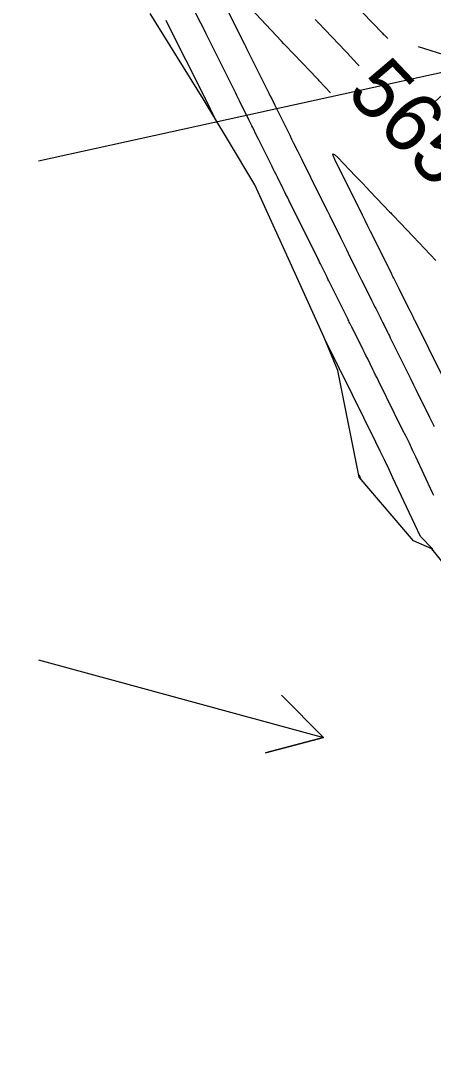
# Model space of a CAD drawing. Extents: x 954385 to 988206, y 1868364 to 1924553.
# Drawn here: x 957405.4 to 957446.7, y 1920279.3 to 1920383 of the extents above; entities that cross this region are included whole.
import ezdxf

# ---------------------------------------------------------------- set-up
doc = ezdxf.new("R2010")
doc.units = 0
for name, color, linetype in [('Default', 7, 'Continuous'), ('Ex_Contour Labels', 7, 'Continuous'), ('Ex_Major Contours', 7, 'Continuous'), ('Ex_Minor Contours', 7, 'Continuous'), ('Perimeter', 7, 'Continuous'), ('Slopes', 7, 'Continuous')]:
    doc.layers.add(name, color=color, linetype=linetype)

msp = doc.modelspace()

# ---------------------------------------------------------------- linework, layer by layer
at = {"layer": 'Default'}
msp.add_arc((966995.78, 1926764.93), 11459.16, 211.460692, 214.075074, dxfattribs=at)
at = {"layer": 'Ex_Major Contours'}
for points in [[(957446.77, 1920335.41), (957446.65, 1920335.68), (957444.97, 1920339.26), (957444.65, 1920339.95), (957444.32, 1920340.63), (957443.99, 1920341.31), (957443.65, 1920341.99), (957441.22, 1920346.9), (957441.08, 1920347.18), (957440.94, 1920347.47), (957440.8, 1920347.75), (957440.67, 1920348.03), (957440.11, 1920349.15), (957439.97, 1920349.44), (957439.83, 1920349.72), (957439.69, 1920350), (957439.55, 1920350.28), (957438.76, 1920351.85), (957438.71, 1920351.96), (957438.66, 1920352.06), (957438.61, 1920352.16), (957438.56, 1920352.27), (957438.35, 1920352.68), (957438.3, 1920352.78), (957438.25, 1920352.89), (957438.2, 1920352.99), (957438.14, 1920353.09), (957436.25, 1920356.9), (957436.16, 1920357.09), (957436.07, 1920357.28), (957435.97, 1920357.47), (957435.88, 1920357.66), (957435.51, 1920358.41), (957435.41, 1920358.6), (957435.32, 1920358.78), (957435.23, 1920358.97), (957435.13, 1920359.16), (957432.23, 1920365), (957432.09, 1920365.29), (957431.95, 1920365.57), (957431.8, 1920365.86), (957431.66, 1920366.14), (957431.1, 1920367.28), (957430.96, 1920367.57), (957430.81, 1920367.85), (957430.67, 1920368.14), (957430.53, 1920368.42), (957429.4, 1920370.7), (957429.2, 1920371.09), (957429.01, 1920371.48), (957428.63, 1920372.26), (957428.53, 1920372.45), (957428.43, 1920372.65), (957428.34, 1920372.84), (957428.24, 1920373.03), (957427.33, 1920374.88), (957427.23, 1920375.08), (957427.13, 1920375.29), (957427.03, 1920375.49), (957426.93, 1920375.7), (957426.52, 1920376.52), (957426.42, 1920376.72), (957426.32, 1920376.93), (957426.22, 1920377.13), (957426.12, 1920377.33), (957424.48, 1920380.59), (957424.21, 1920381.13), (957423.94, 1920381.67), (957423.67, 1920382.21), (957423.4, 1920382.74), (957422.29, 1920384.97)], [(957434.89, 1920383.08), (957435.08, 1920382.88), (957435.11, 1920382.85), (957435.14, 1920382.81), (957435.17, 1920382.78), (957435.2, 1920382.75), (957437.92, 1920379.91), (957438.08, 1920379.74), (957438.35, 1920379.45), (957438.4, 1920379.4), (957438.46, 1920379.34), (957438.51, 1920379.28), (957438.56, 1920379.23), (957439.29, 1920378.46)]]:
    msp.add_lwpolyline(points, dxfattribs=at)
at = {"layer": 'Ex_Minor Contours'}
for points in [[(957436.43, 1920375.74), (957435.28, 1920376.96), (957435.21, 1920377.04), (957435.13, 1920377.12), (957435.05, 1920377.2), (957434.98, 1920377.28), (957434.37, 1920377.92), (957431.88, 1920380.53), (957431.84, 1920380.56), (957431.81, 1920380.59), (957431.78, 1920380.63), (957431.75, 1920380.66), (957431.5, 1920380.93), (957425.31, 1920387.55)], [(957424.57, 1920387.05), (957427.8, 1920380.61), (957427.91, 1920380.41), (957428.01, 1920380.2), (957428.11, 1920380), (957428.21, 1920379.8), (957428.61, 1920379), (957428.71, 1920378.79), (957428.81, 1920378.59), (957428.91, 1920378.39), (957429.01, 1920378.19), (957430.24, 1920375.7), (957430.38, 1920375.42), (957430.52, 1920375.14), (957430.79, 1920374.59), (957430.86, 1920374.45), (957430.93, 1920374.31), (957431, 1920374.17), (957431.06, 1920374.03), (957432.33, 1920371.49), (957432.52, 1920371.1), (957432.72, 1920370.7), (957433.11, 1920369.92), (957433.21, 1920369.72), (957433.31, 1920369.52), (957433.41, 1920369.32), (957433.5, 1920369.13), (957435.36, 1920365.38), (957435.61, 1920364.89), (957435.85, 1920364.39), (957436.1, 1920363.9), (957436.34, 1920363.41), (957437.42, 1920361.24), (957437.62, 1920360.85), (957437.81, 1920360.45), (957438.01, 1920360.06), (957438.2, 1920359.67), (957439.03, 1920357.99), (957439.2, 1920357.65), (957439.37, 1920357.3), (957439.54, 1920356.96), (957439.72, 1920356.62), (957440.53, 1920354.97), (957440.64, 1920354.76), (957440.74, 1920354.56), (957440.84, 1920354.35), (957440.95, 1920354.14), (957441.38, 1920353.28), (957441.47, 1920353.09), (957441.57, 1920352.9), (957441.66, 1920352.71), (957441.76, 1920352.52), (957442.13, 1920351.77), (957442.23, 1920351.58), (957442.32, 1920351.39), (957442.41, 1920351.2), (957442.51, 1920351.01), (957443.93, 1920348.13), (957444.2, 1920347.59), (957444.47, 1920347.05), (957444.74, 1920346.5), (957445.01, 1920345.96), (957446.35, 1920343.25), (957446.58, 1920342.78), (957446.81, 1920342.31)], [(957424.9, 1920373.09), (957423.88, 1920375.15), (957423.84, 1920375.24), (957423.83, 1920375.26), (957423.81, 1920375.29), (957420.02, 1920382.84), (957419.95, 1920382.99)], [(957439.64, 1920383.8), (957441.63, 1920381.72), (957441.71, 1920381.64), (957441.78, 1920381.56), (957441.86, 1920381.48), (957441.93, 1920381.41), (957442.15, 1920381.18)], [(957447.67, 1920347.29), (957444.9, 1920352.89), (957444.85, 1920352.98), (957444.81, 1920353.06), (957444.77, 1920353.15), (957444.73, 1920353.23), (957444.56, 1920353.57), (957444.52, 1920353.66), (957444.47, 1920353.74), (957444.43, 1920353.83), (957444.39, 1920353.91), (957443.37, 1920355.95), (957443.3, 1920356.09), (957443.23, 1920356.23), (957443.16, 1920356.37), (957443.09, 1920356.5), (957442.82, 1920357.05), (957442.75, 1920357.19), (957442.68, 1920357.33), (957442.61, 1920357.47), (957442.55, 1920357.6), (957440.44, 1920361.85), (957440.37, 1920361.99), (957440.3, 1920362.13), (957440.24, 1920362.26), (957440.17, 1920362.4), (957439.9, 1920362.94), (957439.76, 1920363.22), (957439.63, 1920363.49), (957436.86, 1920369.06), (957436.67, 1920369.48), (957436.66, 1920369.65), (957436.82, 1920369.58), (957437.15, 1920369.27), (957438.93, 1920367.4), (957439.29, 1920367.02), (957439.65, 1920366.65), (957440.01, 1920366.27), (957440.37, 1920365.89), (957442.36, 1920363.8), (957442.45, 1920363.71), (957442.53, 1920363.62), (957442.62, 1920363.53), (957442.7, 1920363.44), (957443.39, 1920362.73), (957444.71, 1920361.34), (957446.99, 1920358.96)], [(957446.67, 1920329.96), (957446.64, 1920330.04), (957446.63, 1920330.06), (957446.62, 1920330.07), (957446.61, 1920330.08), (957446.6, 1920330.09), (957445.47, 1920331.27), (957445.43, 1920331.31), (957445.42, 1920331.32), (957445.41, 1920331.33), (957445.41, 1920331.34), (957445.4, 1920331.35), (957445.17, 1920331.85), (957445.14, 1920331.91), (957442.68, 1920337.17), (957442.25, 1920338.06), (957441.83, 1920338.96), (957441.39, 1920339.85), (957440.96, 1920340.74), (957437.44, 1920347.85), (957437.4, 1920347.92), (957437.35, 1920348.02), (957437.33, 1920348.06), (957437.32, 1920348.08), (957435.87, 1920350.98)], [(957439.24, 1920337.51), (957439.32, 1920337.34), (957439.33, 1920337.32), (957439.35, 1920337.29), (957439.36, 1920337.26), (957439.37, 1920337.23), (957439.46, 1920337.05)]]:
    msp.add_lwpolyline(points, dxfattribs=at)
at = {"layer": 'Perimeter'}
msp.add_lwpolyline([(957489.21, 1920274.25), (957480.9, 1920280.7), (957474.77, 1920288.63), (957474.48, 1920289.32), (957474.48, 1920289.32), (957470.67, 1920297.93), (957464.77, 1920306.01), (957458.75, 1920313.92), (957458.71, 1920313.98), (957454.69, 1920319.76), (957452.93, 1920322.21), (957446.59, 1920330.05), (957444.73, 1920330.87), (957439.29, 1920337.25), (957437.15, 1920347.92), (957435.77, 1920351.23), (957433.04, 1920357.26), (957428.82, 1920366.52), (957426.1, 1920371.09), (957423.66, 1920375.15), (957418.35, 1920383.68)], dxfattribs=at)
at = {"layer": 'Slopes'}
for points in [[(957407.13, 1920368.93), (957450.95, 1920378.54), (957446.52, 1920374.5), (957450.95, 1920378.54), (957445.24, 1920380.36)], [(957407.13, 1920318.93), (957435.71, 1920311.14), (957429.91, 1920309.61), (957435.71, 1920311.14), (957431.49, 1920315.4)]]:
    msp.add_lwpolyline(points, dxfattribs=at)

# ---------------------------------------------------------------- texts
at = {"layer": 'Ex_Contour Labels'}
msp.add_text('565', height=6, rotation=313.5836, dxfattribs=at).set_placement((957437.86, 1920375.62))

doc.saveas('drawing.dxf')
